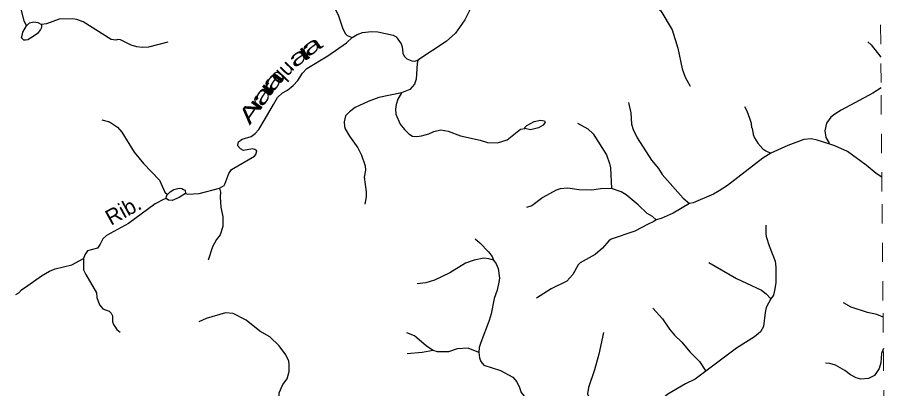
# Model space of a CAD drawing. Extents: x 346.5 to 372.4, y 7400.3 to 7428.2.
# Drawn here: x 367.755 to 372.279, y 7413.666 to 7415.59 of the extents above; entities that cross this region are included whole.
import ezdxf
from ezdxf.enums import TextEntityAlignment as Align

# ---------------------------------------------------------------- set-up
doc = ezdxf.new("R2010")
doc.units = 0
doc.header["$LTSCALE"] = 0.032
doc.linetypes.add('SHORT_DASHED', pattern=[2.7, 1.5, -1.2])
for name, color, linetype, lineweight in [('2', 7, 'Continuous', 25), ('53', 7, 'SHORT_DASHED', 13), ('7', 7, 'Continuous', 25)]:
    doc.layers.add(name, color=color, linetype=linetype, lineweight=lineweight)
doc.layers.add('61', color=7, linetype='Continuous')

msp = doc.modelspace()

# ---------------------------------------------------------------- linework, layer by layer
at = {"layer": '2'}
for points in [[(367.8026, 7415.5476), (367.8177, 7415.5627), (367.8407, 7415.5672), (367.8622, 7415.5645), (367.8797, 7415.5543), (367.8796, 7415.5383), (367.8758, 7415.5277), (367.8588, 7415.5064), (367.8364, 7415.4909), (367.8094, 7415.4748), (367.797, 7415.4719), (367.7883, 7415.4727), (367.7826, 7415.477), (367.7767, 7415.4846), (367.7792, 7415.4974), (367.783, 7415.5145)], [(370.3909, 7415.0143), (370.3908, 7415.019), (370.4013, 7415.0307), (370.439, 7415.0509), (370.4723, 7415.0586), (370.4918, 7415.0539), (370.4966, 7415.048), (370.4859, 7415.0319), (370.4615, 7415.0184), (370.4201, 7415.007)], [(368.5276, 7414.6509), (368.5293, 7414.6633), (368.5344, 7414.6716), (368.5488, 7414.6858), (368.5682, 7414.6984), (368.5951, 7414.7058), (368.6092, 7414.7042), (368.6186, 7414.6989), (368.6269, 7414.6947), (368.6276, 7414.677), (368.5946, 7414.6561), (368.5591, 7414.6415), (368.5396, 7414.643)]]:
    msp.add_lwpolyline(points, close=True, dxfattribs=at)
at = {"layer": '53'}
msp.add_lwpolyline([(372.279, 7410.733), (372.2741, 7411.2979), (372.2732, 7411.3718), (372.2724, 7411.4211), (372.2704, 7411.5196), (372.2681, 7411.6182), (372.2651, 7411.7496), (372.2637, 7411.8153), (372.2621, 7411.9138), (372.2616, 7411.9631), (372.2614, 7412.0147), (372.2615, 7412.0491), (372.262, 7412.118), (372.2628, 7412.1868), (372.264, 7412.2786), (372.2643, 7412.3245), (372.2645, 7412.3933), (372.2643, 7412.4277), (372.2594, 7412.9926), (372.2545, 7413.5575), (372.2496, 7414.1225), (372.2447, 7414.6874), (372.2399, 7415.2523), (372.235, 7415.8172)], dxfattribs=at)
at = {"layer": '7'}
for points in [[(367.7635, 7415.9752), (367.7652, 7415.9431), (367.7852, 7415.8458), (367.7899, 7415.8012), (367.79, 7415.747), (367.7748, 7415.6848), (367.7716, 7415.6402), (367.7884, 7415.5733), (367.8026, 7415.5476)], [(371.0385, 7415.9209), (371.0319, 7415.865), (371.0327, 7415.7932), (371.0351, 7415.7645), (371.0487, 7415.7072), (371.0909, 7415.6283), (371.0957, 7415.6251), (371.1546, 7415.527), (371.1849, 7415.4314), (371.2073, 7415.3246), (371.2224, 7415.2816), (371.2495, 7415.2346)], [(369.1503, 7415.7789), (369.2069, 7415.7821), (369.2834, 7415.7813), (369.3065, 7415.7677), (369.3416, 7415.7199), (369.3799, 7415.6832), (369.3799, 7415.6777), (369.3902, 7415.6641), (369.4205, 7415.6036), (369.4428, 7415.5366), (369.458, 7415.5071), (369.4683, 7415.496), (369.4928, 7415.4857)], [(370.1628, 7415.7561), (370.1266, 7415.6801), (370.1234, 7415.6673), (370.0788, 7415.5781), (370.031, 7415.5095), (369.9816, 7415.4665), (369.8346, 7415.3692)], [(368.5367, 7415.4617), (368.4355, 7415.437), (368.4052, 7415.4346), (368.3749, 7415.4378), (368.3462, 7415.4473), (368.2904, 7415.4736), (368.2761, 7415.4752), (368.2665, 7415.4728), (368.2418, 7415.4768), (368.0976, 7415.5677), (368.0641, 7415.5804), (368.0418, 7415.5836), (367.9717, 7415.582), (367.9063, 7415.5581), (367.8797, 7415.5543)], [(368.8042, 7414.7048), (368.8284, 7414.7197), (368.8323, 7414.7253), (368.8539, 7414.7811), (368.8674, 7414.8018), (368.9862, 7414.8719), (368.9941, 7414.8799), (368.9981, 7414.899), (368.9886, 7414.9062), (368.9758, 7414.9086), (368.9288, 7414.9006), (368.9136, 7414.9086), (368.9001, 7414.9246), (368.9017, 7414.9397), (368.9033, 7414.9453), (368.9232, 7414.9588), (368.9694, 7414.9739), (368.9902, 7414.9883), (369.0093, 7415.009), (369.0411, 7415.0648), (369.0858, 7415.1397), (369.1057, 7415.1756), (369.132, 7415.1987), (369.1575, 7415.2138), (369.1878, 7415.2377), (369.2109, 7415.2641), (369.2364, 7415.3023), (369.2587, 7415.3262), (369.3679, 7415.3915), (369.4635, 7415.4593), (369.4928, 7415.4857)], [(369.4928, 7415.4857), (369.5193, 7415.5023), (369.5464, 7415.5127), (369.5942, 7415.5175), (369.6261, 7415.5151), (369.7058, 7415.4991), (369.7218, 7415.4904), (369.7472, 7415.4537), (369.7528, 7415.4378), (369.7568, 7415.4059), (369.764, 7415.39), (369.7767, 7415.3764), (369.8035, 7415.365), (369.8189, 7415.3641), (369.8346, 7415.3692)], [(372.1708, 7415.4633), (372.1891, 7415.4481), (372.2387, 7415.3838)], [(369.8346, 7415.3692), (369.8305, 7415.3519), (369.8254, 7415.2704), (369.8166, 7415.2449), (369.7927, 7415.217), (369.7491, 7415.2003)], [(372.2401, 7415.2255), (372.1979, 7415.1979), (372.0329, 7415.1094), (371.9994, 7415.0895), (371.9795, 7415.0736), (371.9564, 7415.0425), (371.9476, 7415.0027), (371.954, 7414.9676), (371.9682, 7414.9426), (371.9686, 7414.9347)], [(369.7491, 7415.2003), (369.6325, 7415.1756), (369.5767, 7415.1541), (369.5098, 7415.1238), (369.4795, 7415.1015), (369.4595, 7415.0808), (369.4516, 7415.0489), (369.4532, 7415.025), (369.458, 7415.0122), (369.4803, 7414.974), (369.5225, 7414.9142), (369.5424, 7414.8767), (369.5616, 7414.821), (369.5632, 7414.7986), (369.5552, 7414.762), (369.5671, 7414.6855), (369.5663, 7414.66), (369.56, 7414.6225)], [(369.7491, 7415.2003), (369.7305, 7415.1666), (369.7217, 7415.1397), (369.7186, 7415.1142), (369.7209, 7415.0887), (369.7425, 7415.0377), (369.7656, 7415.009), (369.7879, 7414.9875), (369.8062, 7414.9755), (369.8286, 7414.9724), (369.8541, 7414.9763), (369.8923, 7414.9867), (369.917, 7414.9987), (369.9545, 7415.0074), (369.9927, 7415.0003), (370.0565, 7414.9771), (370.1585, 7414.954), (370.1967, 7414.9421), (370.2477, 7414.9397), (370.2987, 7414.9556), (370.3681, 7415.0106), (370.3909, 7415.0143)], [(370.9283, 7415.1501), (370.9411, 7415.0951), (370.9435, 7415.0377), (370.9522, 7415.009), (370.9729, 7414.966), (371.0487, 7414.8512), (371.0845, 7414.8066), (371.1036, 7414.7755), (371.2126, 7414.6538), (371.2451, 7414.6264)], [(371.5308, 7415.1294), (371.5436, 7415.1063), (371.5571, 7415.068), (371.5651, 7415.0425), (371.5675, 7415.0202), (371.5707, 7415.017), (371.5754, 7414.9835), (371.5834, 7414.9668), (371.6009, 7414.9389), (371.6264, 7414.9094), (371.6416, 7414.8982), (371.6671, 7414.8871)], [(368.194, 7415.06), (368.2331, 7415.0497), (368.2745, 7415.021), (368.2976, 7414.9955), (368.3614, 7414.8911), (368.4092, 7414.8337), (368.4929, 7414.7468), (368.5207, 7414.6847), (368.5344, 7414.6716)], [(370.6645, 7415.0417), (370.7179, 7415.013), (370.7442, 7414.9867), (370.8144, 7414.8783), (370.8303, 7414.8337), (370.8351, 7414.8114), (370.8407, 7414.703)], [(371.9686, 7414.9347), (371.9086, 7414.9548), (371.8783, 7414.9612), (371.8384, 7414.9572), (371.7556, 7414.9261), (371.6671, 7414.8871)], [(372.244, 7414.7627), (372.2138, 7414.7819), (372.162, 7414.8249), (372.0664, 7414.895), (371.9994, 7414.9245), (371.9686, 7414.9347)], [(371.6671, 7414.8871), (371.6257, 7414.86), (371.4431, 7414.7197), (371.4001, 7414.691), (371.3698, 7414.6735), (371.2637, 7414.6298), (371.2451, 7414.6264)], [(368.6276, 7414.677), (368.64, 7414.6742), (368.6985, 7414.6767), (368.8042, 7414.7048)], [(368.8042, 7414.7048), (368.8092, 7414.6839), (368.8076, 7414.6584), (368.8108, 7414.6074), (368.8228, 7414.5564), (368.8228, 7414.5061), (368.8076, 7414.4639), (368.7885, 7414.4384), (368.7686, 7414.4002), (368.7463, 7414.3324)], [(370.8407, 7414.703), (370.7833, 7414.7022), (370.7387, 7414.695), (370.6701, 7414.6958), (370.6127, 7414.7054), (370.5745, 7414.7022), (370.5522, 7414.6942), (370.4828, 7414.656), (370.4263, 7414.6129), (370.3984, 7414.6042)], [(371.0717, 7414.5412), (371.0535, 7414.5587), (371.0248, 7414.5747), (370.9785, 7414.6185), (370.9156, 7414.6711), (370.8901, 7414.6855), (370.8407, 7414.703)], [(368.5276, 7414.6509), (368.5179, 7414.6486), (368.4706, 7414.6241), (368.3327, 7414.5221), (368.2187, 7414.4591), (368.198, 7414.4424), (368.1852, 7414.4145), (368.1709, 7414.3946), (368.1199, 7414.3802), (368.1056, 7414.3596), (368.0981, 7414.3406)], [(371.2451, 7414.6264), (371.161, 7414.5763), (371.0989, 7414.5476), (371.0717, 7414.5412)], [(371.0717, 7414.5412), (371.0597, 7414.5319), (371.0303, 7414.5189), (370.9618, 7414.4814), (370.8391, 7414.4416), (370.8263, 7414.4328), (370.7936, 7414.3938), (370.7546, 7414.3611), (370.6773, 7414.3189), (370.6677, 7414.3077), (370.639, 7414.2567), (370.6088, 7414.2224), (370.5266, 7414.1834), (370.451, 7414.1356)], [(371.6408, 7414.5125), (371.6408, 7414.4703), (371.644, 7414.4544), (371.6583, 7414.4065), (371.6902, 7414.3268), (371.6934, 7414.295), (371.6934, 7414.2153), (371.6886, 7414.1834), (371.6807, 7414.1505), (371.6676, 7414.1312)], [(370.1322, 7414.4432), (370.1569, 7414.4225), (370.2023, 7414.3755), (370.2199, 7414.3506), (370.2274, 7414.332)], [(367.7472, 7414.1546), (367.7624, 7414.1628), (367.7764, 7414.1778), (367.8091, 7414.2009), (367.8808, 7414.2503), (367.9223, 7414.2742), (367.9509, 7414.2862), (368.0386, 7414.3085), (368.0981, 7414.3406)], [(368.0981, 7414.3406), (368.0984, 7414.2822), (368.1103, 7414.2567), (368.1661, 7414.1619), (368.1685, 7414.1388), (368.1812, 7414.1005), (368.198, 7414.0798), (368.2315, 7414.067), (368.2426, 7414.0567), (368.249, 7414.0431), (368.249, 7414.012), (368.2538, 7413.9985), (368.2713, 7413.9722), (368.2896, 7413.9587)], [(370.2274, 7414.332), (370.2031, 7414.3396), (370.1776, 7414.3428), (370.1266, 7414.3316), (370.0828, 7414.3157), (370.0007, 7414.2654), (369.921, 7414.228), (369.8764, 7414.2137), (369.8309, 7414.2089)], [(370.2274, 7414.332), (370.2414, 7414.3133), (370.2525, 7414.2894), (370.2589, 7414.2392), (370.2573, 7414.2264), (370.2469, 7414.177), (370.231, 7414.1324), (370.2151, 7414.0543), (370.2047, 7414.0192), (370.1609, 7413.9045), (370.1537, 7413.879), (370.1519, 7413.8533)], [(371.3451, 7414.3205), (371.4886, 7414.2376), (371.6193, 7414.1762), (371.6432, 7414.1571), (371.6676, 7414.1312)], [(371.6676, 7414.1312), (371.6432, 7414.0862), (371.6376, 7414.0607), (371.6296, 7413.9881), (371.6137, 7413.9602), (371.5834, 7413.9339), (371.4886, 7413.875), (371.33, 7413.7559)], [(371.055, 7414.0838), (371.1052, 7414.0272), (371.1419, 7413.9746), (371.1682, 7413.9435), (371.2057, 7413.9068), (371.2471, 7413.8566), (371.2973, 7413.8056), (371.33, 7413.7559)], [(372.2503, 7414.0359), (372.2178, 7414.0495), (372.17, 7414.0607), (372.0839, 7414.0885), (372.0449, 7414.1109)], [(369.0978, 7413.4204), (369.0818, 7413.4614), (369.081, 7413.4821), (369.0874, 7413.4908), (369.1105, 7413.5012), (369.12, 7413.51), (369.124, 7413.5251), (369.1137, 7413.616), (369.1153, 7413.6447), (369.1336, 7413.6877), (369.1559, 7413.7164), (369.1671, 7413.7538), (369.1671, 7413.7929), (369.1639, 7413.8088), (369.1487, 7413.8407), (369.1145, 7413.8885), (369.0659, 7413.9339), (369.0141, 7413.9634), (368.9439, 7414.0216), (368.8762, 7414.0551), (368.8355, 7414.0591), (368.7351, 7414.0288), (368.6977, 7414.0128)], [(369.9138, 7413.8633), (369.8795, 7413.8853), (369.8174, 7413.9395), (369.7767, 7413.9547)], [(370.7984, 7413.9563), (370.7753, 7413.8439), (370.7522, 7413.7634), (370.7211, 7413.6718), (370.7155, 7413.6383), (370.7255, 7413.6166)], [(369.9138, 7413.8633), (369.8572, 7413.8534), (369.7799, 7413.8455)], [(370.1519, 7413.8533), (370.0963, 7413.8758), (370.0389, 7413.8718), (369.9943, 7413.8566), (369.9369, 7413.8566), (369.9138, 7413.8633)], [(372.2518, 7413.8731), (372.2425, 7413.8471), (372.2385, 7413.7993), (372.2305, 7413.7698), (372.2058, 7413.7339), (372.1748, 7413.7188), (372.1349, 7413.7148), (372.111, 7413.7219), (372.0807, 7413.7371), (372.052, 7413.7594), (372.0026, 7413.7873), (371.9739, 7413.7961), (371.9508, 7413.7977)], [(370.1519, 7413.8533), (370.1553, 7413.8248), (370.1624, 7413.8056), (370.1776, 7413.7881), (370.2637, 7413.7594), (370.3274, 7413.7251), (370.3481, 7413.7012), (370.3633, 7413.6718), (370.372, 7413.6463), (370.4031, 7413.608), (370.443, 7413.5721), (370.498, 7413.5394), (370.5244, 7413.5277)], [(371.33, 7413.7559), (371.2742, 7413.7148), (371.2248, 7413.6909), (371.1324, 7413.6375), (371.0925, 7413.6048), (371.059, 7413.5634), (371.0319, 7413.5156), (371.0256, 7413.4996), (371.02, 7413.4677), (371.0184, 7413.4088), (371.0396, 7413.3201)]]:
    msp.add_lwpolyline(points, dxfattribs=at)

# ---------------------------------------------------------------- texts
at = {"layer": '61'}
for s, rotation, width, p in [('r', 35.028, 1.75, (369.2717, 7415.3861)), ('a', 35.028, 1.75, (369.3053, 7415.4108)), ('a', 33.833, 1.7, (369.2349, 7415.3538)), ('r', 52.914, 1.85, (369.0863, 7415.209)), ('a', 52.914, 1.8, (369.1123, 7415.2385)), ('a', 54.799, 1.75, (369.0573, 7415.164)), ('r', 55.145, 1.75, (369.0294, 7415.127)), ('A', 55.145, 1.65, (368.995, 7415.0771))]:
    msp.add_text(s, height=0.08, rotation=rotation, dxfattribs=dict(at, width=width)).set_placement(p, align=Align.CENTER)
for s, rotation, p in [('u', 46.565, (369.1773, 7415.3031)), ('q', 46.565, (369.1343, 7415.2612)), ('Rib.', 28.75, (368.3239, 7414.5557))]:
    msp.add_text(s, height=0.08, rotation=rotation, dxfattribs=at).set_placement(p, align=Align.CENTER)

doc.saveas('drawing.dxf')
